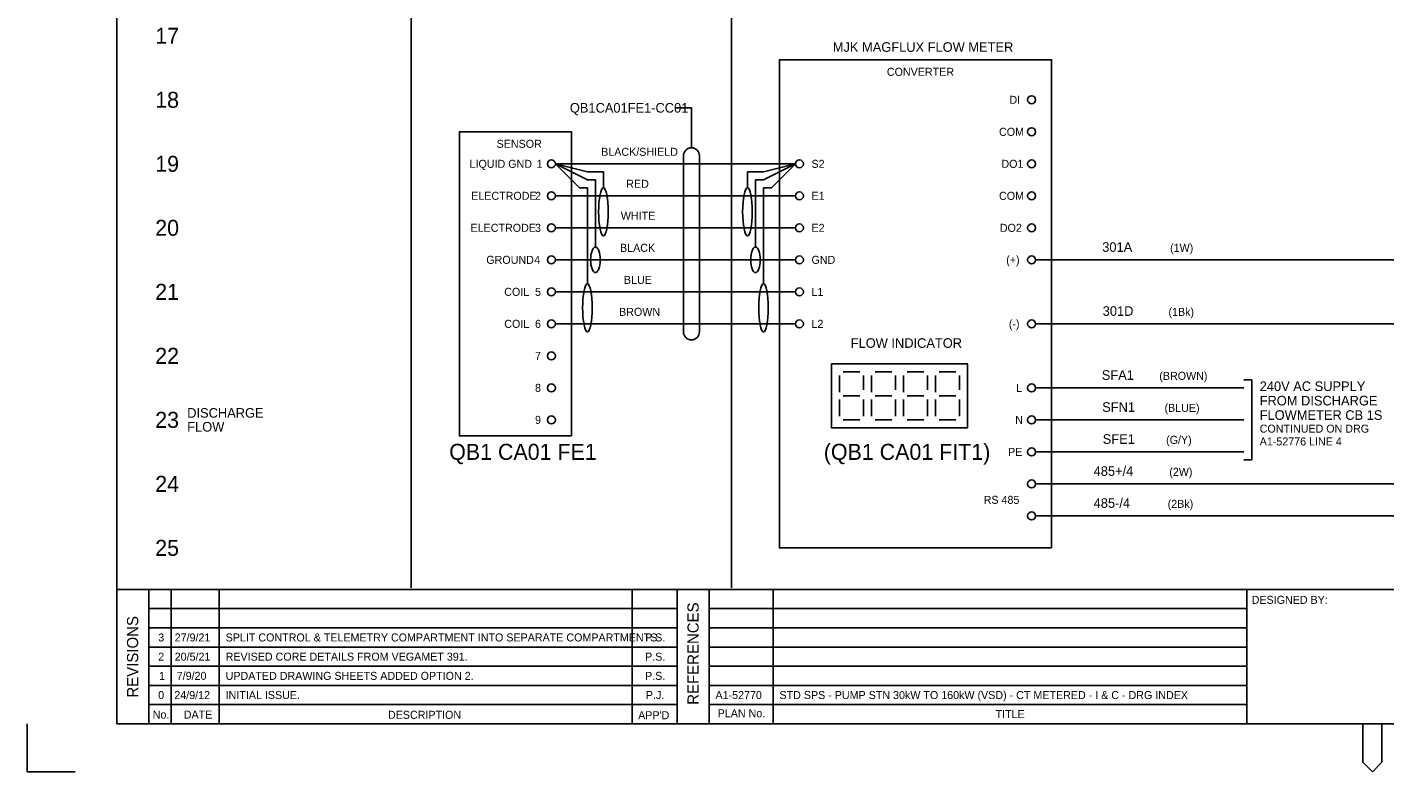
# Model space of a CAD drawing. Extents: x 0 to 841, y 0 to 594.
# Drawn here: x 0 to 424.1, y 0 to 232.7 of the extents above; entities that cross this region are included whole.
import ezdxf

# ---------------------------------------------------------------- set-up
doc = ezdxf.new("R2010")
doc.units = 0
for name, color, linetype in [('A1BORDER', 7, 'Continuous'), ('Level 1', 7, 'Continuous'), ('Level 10', 7, 'Continuous'), ('Level 2', 7, 'Continuous')]:
    doc.layers.add(name, color=color, linetype=linetype)

msp = doc.modelspace()

# ---------------------------------------------------------------- linework, layer by layer
at = {"layer": 'A1BORDER'}
for p, q in [((28, 581), (28, 15)), ((28, 57), (829, 57)), ((38, 15), (38, 57)), ((45, 15), (45, 57)), ((60, 15), (60, 57)), ((189, 15), (189, 57)), ((203, 15), (203, 57)), ((213, 15), (213, 57)), ((233, 15), (233, 57)), ((381, 15), (381, 57)), ((203, 51), (38, 51)), ((213, 51), (381, 51)), ((203, 45), (38, 45)), ((213, 45), (381, 45)), ((203, 39), (38, 39)), ((213, 39), (381, 39)), ((203, 33), (38, 33)), ((213, 33), (381, 33)), ((38, 27), (203, 27)), ((213, 27), (381, 27)), ((203, 21), (38, 21)), ((213, 21), (381, 21)), ((0, 0), (0, 15)), ((829, 15), (28, 15)), ((417.19, 15), (417.19, 3)), ((423.19, 15), (423.19, 3)), ((0, 0), (15, 0)), ((417.19, 3), (420.19, 0)), ((423.19, 3), (420.19, 0))]:
    msp.add_line(p, q, dxfattribs=at)
at = {"layer": 'Level 1'}
for p, q in [((120, 57.5), (120, 581)), ((220, 57.5), (220, 581)), ((312.5, 210), (312.5, 210)), ((315, 210), (315, 210)), ((207.5, 207.5), (202.5, 207.5)), ((207.5, 207.5), (207.5, 195)), ((312.5, 200), (312.5, 200)), ((315, 200), (315, 200)), ((205, 192.5), (205, 137.5)), ((210, 192.5), (210, 137.5)), ((162.5, 190), (162.5, 190)), ((240, 190), (165, 190)), ((165, 190), (165, 190)), ((175, 187.5), (165, 190)), ((175, 185), (165, 190)), ((172.5, 182.5), (165, 190)), ((180, 187.5), (175, 187.5)), ((180, 182.5), (180, 187.5)), ((225, 182.5), (225, 187.5)), ((225, 187.5), (230, 187.5)), ((230, 187.5), (240, 190)), ((230, 185), (240, 190)), ((232.5, 182.5), (240, 190)), ((240, 190), (240, 190)), ((242.5, 190), (242.5, 190)), ((312.5, 190), (312.5, 190)), ((315, 190), (315, 190)), ((175, 182.5), (172.5, 182.5)), ((175, 185), (177.5, 185)), ((175, 152.5), (175, 182.5)), ((177.5, 164), (177.5, 185)), ((227.5, 164), (227.5, 185)), ((230, 185), (227.5, 185)), ((230, 152.5), (230, 182.5)), ((230, 182.5), (232.5, 182.5)), ((162.5, 180), (162.5, 180)), ((240, 180), (165, 180)), ((165, 180), (165, 180)), ((240, 180), (240, 180)), ((242.5, 180), (242.5, 180)), ((312.5, 180), (312.5, 180)), ((315, 180), (315, 180)), ((162.5, 170), (162.5, 170)), ((240, 170), (165, 170)), ((165, 170), (165, 170)), ((240, 170), (240, 170)), ((242.5, 170), (242.5, 170)), ((312.5, 170), (312.5, 170)), ((315, 170), (315, 170)), ((162.5, 160), (162.5, 160)), ((165, 160), (165, 160)), ((177.5, 160), (165, 160)), ((240, 160), (165, 160)), ((240, 160), (240, 160)), ((242.5, 160), (242.5, 160)), ((312.5, 160), (312.5, 160)), ((315, 160), (315, 160)), ((602.5, 160), (315, 160)), ((162.5, 150), (162.5, 150)), ((240, 150), (165, 150)), ((165, 150), (165, 150)), ((240, 150), (240, 150)), ((242.5, 150), (242.5, 150)), ((162.5, 140), (162.5, 140)), ((240, 140), (165, 140)), ((165, 140), (165, 140)), ((240, 140), (240, 140)), ((242.5, 140), (242.5, 140)), ((312.5, 140), (312.5, 140)), ((315, 140), (315, 140)), ((602.5, 140), (315, 140)), ((162.5, 130), (162.5, 130)), ((165, 130), (165, 130)), ((162.5, 120), (162.5, 120)), ((165, 120), (165, 120)), ((312.5, 120), (312.5, 120)), ((315, 120), (315, 120)), ((315, 120), (380, 120)), ((162.5, 110), (162.5, 110)), ((165, 110), (165, 110)), ((312.5, 110), (312.5, 110)), ((315, 110), (315, 110)), ((315, 110), (380, 110)), ((312.5, 100), (312.5, 100)), ((315, 100), (315, 100)), ((315, 100), (380, 100)), ((315, 90), (602.5, 90)), ((315, 80), (602.5, 80))]:
    msp.add_line(p, q, dxfattribs=at)
for points in [[(320, 70), (235, 70), (235, 222.5), (320, 222.5)], [(170, 105), (135, 105), (135, 200), (170, 200)], [(251.25, 127.5), (293.75, 127.5), (293.75, 107.5), (251.25, 107.5)]]:
    msp.add_lwpolyline(points, close=True, dxfattribs=at)
msp.add_lwpolyline([(380, 122.5), (382.5, 122.5), (382.5, 97.5), (380, 97.5)], dxfattribs=at)
for centre, start, end in [((207.5, 192.5), 0, 180), ((207.5, 137.5), 180, 0)]:
    msp.add_arc(centre, 2.5, start, end, dxfattribs=at)
for centre, major_axis, ratio in [((180, 175), (0, -7.5), 0.2), ((225, 175), (0, 7.5), 0.2), ((177.5, 160), (0, -4), 0.375), ((227.5, 160), (0, 4), 0.375), ((175, 145), (0, -7.5), 0.2), ((230, 145), (0, 7.5), 0.2)]:
    msp.add_ellipse(centre, major_axis=major_axis, ratio=ratio, dxfattribs=at)
at = {"layer": 'Level 10'}
for centre in [(313.75, 210), (313.75, 200), (163.75, 190), (241.25, 190), (313.75, 190), (163.75, 180), (241.25, 180), (313.75, 180), (163.75, 170), (241.25, 170), (313.75, 170), (163.75, 160), (241.25, 160), (313.75, 160), (163.75, 150), (241.25, 150), (163.75, 140), (241.25, 140), (313.75, 140), (163.75, 130), (163.75, 120), (313.75, 120), (163.75, 110), (313.75, 110), (313.75, 100), (313.75, 90), (313.75, 80)]:
    msp.add_circle(centre, 1.25, dxfattribs=at)
at = {"layer": 'Level 2'}
for p, q in [((253.75, 123.88), (253.75, 118.63)), ((254.88, 125), (260.12, 125)), ((261.25, 123.88), (261.25, 119.38)), ((263.75, 123.88), (263.75, 118.63)), ((264.88, 125), (270.12, 125)), ((271.25, 123.88), (271.25, 119.38)), ((273.75, 123.88), (273.75, 118.63)), ((274.88, 125), (280.12, 125)), ((281.25, 123.88), (281.25, 119.38)), ((283.75, 123.88), (283.75, 118.63)), ((284.88, 125), (290.12, 125)), ((291.25, 123.88), (291.25, 119.38)), ((253.75, 116.38), (253.75, 111.13)), ((254.88, 117.5), (260.12, 117.5)), ((261.25, 116.38), (261.25, 111.13)), ((263.75, 116.38), (263.75, 111.13)), ((264.88, 117.5), (270.12, 117.5)), ((271.25, 116.38), (271.25, 111.13)), ((273.75, 116.38), (273.75, 111.13)), ((274.88, 117.5), (280.12, 117.5)), ((281.25, 116.38), (281.25, 111.13)), ((283.75, 116.38), (283.75, 111.13)), ((284.88, 117.5), (290.12, 117.5)), ((291.25, 116.38), (291.25, 111.13)), ((254.88, 110), (260.12, 110)), ((264.88, 110), (270.12, 110)), ((274.88, 110), (280.12, 110)), ((284.88, 110), (290.12, 110))]:
    msp.add_line(p, q, dxfattribs=at)

# ---------------------------------------------------------------- texts
at = {"layer": 'A1BORDER'}
for s, p in [('REFERENCES', (209.76, 20.96)), ('REVISIONS', (34.68, 23.2))]:
    msp.add_text(s, height=3.5, rotation=90, dxfattribs=at).set_placement(p)
for s, p in [('DESIGNED BY:', (382.5, 52.5)), ('No.', (39.21, 16.65)), ('DATE', (48.92, 16.65)), ('DESCRIPTION', (112.71, 16.57)), ("APP'D", (190.85, 16.44)), ('PLAN No.', (215.69, 17.06)), ('TITLE', (302.5, 16.81))]:
    msp.add_text(s, height=2.5, dxfattribs=at).set_placement(p)
at = {"layer": 'Level 1'}
for s, height, p in [('17', 5, (40, 227.5)), ('MJK MAGFLUX FLOW METER', 3, (251.65, 225)), ('MJK MAGFLUX FLOW METER', 3, (251.65, 225)), ('CONVERTER', 2.5, (268.55, 217.5)), ('18', 5, (40, 207.5)), ('QB1CA01FE1-CC01', 3, (169.52, 206)), ('DI', 2.5, (306.81, 208.75)), ('COM', 2.5, (303.58, 198.75)), ('SENSOR', 2.5, (146.64, 195)), ('BLACK/SHIELD', 2.5, (179.3, 192.5)), ('19', 5, (40, 187.5)), ('LIQUID GND', 2.5, (138.2, 188.75)), ('1', 2.5, (159.13, 188.75)), ('S2', 2.5, (245, 188.75)), ('DO1', 2.5, (304.32, 188.75)), ('RED', 2.5, (187.14, 182.5)), ('ELECTRODE', 2.5, (138.69, 178.75)), ('2', 2.5, (158.64, 178.75)), ('E1', 2.5, (245, 178.75)), ('COM', 2.5, (303.58, 178.75)), ('WHITE', 2.5, (185.44, 172.5)), ('20', 5, (40, 167.5)), ('ELECTRODE', 2.5, (138.49, 168.75)), ('3', 2.5, (158.64, 168.75)), ('E2', 2.5, (245, 168.75)), ('DO2', 2.5, (303.83, 168.75)), ('301A', 3, (335.82, 162.5)), ('GROUND', 2.5, (143.42, 158.75)), ('4', 2.5, (158.39, 158.75)), ('BLACK', 2.5, (185.19, 162.5)), ('GND', 2.5, (245, 158.75)), ('(+)', 2.5, (305.82, 158.75)), ('(1W)', 2.5, (357.01, 162.5)), ('BLUE', 2.5, (186.41, 152.5)), ('21', 5, (40, 147.5)), ('COIL', 2.5, (149.02, 148.75)), ('5', 2.5, (158.64, 148.75)), ('L1', 2.5, (245, 148.75)), ('BROWN', 2.5, (184.9, 142.5)), ('301D', 3, (335.96, 142.5)), ('(1Bk)', 2.5, (356.51, 142.5)), ('COIL', 2.5, (149.03, 138.75)), ('6', 2.5, (158.64, 138.75)), ('L2', 2.5, (245, 138.75)), ('(-)', 2.5, (306.64, 138.75)), ('22', 5, (40, 127.5)), ('7', 2.5, (158.64, 128.75)), ('SFA1', 3, (335.67, 122.5)), ('(BROWN)', 2.5, (353.65, 122.5)), ('8', 2.5, (158.64, 118.75)), ('L', 2.5, (308.88, 118.75)), ('240V AC SUPPLY', 3, (385, 119)), ('SFN1', 3, (335.81, 112.5)), ('(BLUE)', 2.5, (355.27, 112.5)), ('FROM DISCHARGE', 3, (385, 114.5)), ('23', 5, (40, 107.5)), ('DISCHARGE', 3, (50, 110.67)), ('9', 2.5, (158.64, 108.75)), ('N', 2.5, (308.62, 108.75)), ('FLOWMETER CB 1S', 3, (385, 110)), ('FLOW', 3, (50, 106.33)), ('CONTINUED ON DRG', 2.5, (385, 106)), ('QB1 CA01 FE1', 5, (131.83, 97.5)), ('(QB1 CA01 FIT1)', 5, (248.84, 97.5)), ('SFE1', 3, (335.97, 102.5)), ('(G/Y)', 2.5, (355.77, 102.5)), ('A1-52776 LINE 4', 2.5, (385, 102)), ('PE', 2.5, (306.41, 98.75)), ('485+/4', 3, (333.13, 92.5)), ('(2W)', 2.5, (356.76, 92.5)), ('24', 5, (40, 87.5)), ('RS 485', 2.5, (298.79, 83.75)), ('485-/4', 3, (333.13, 82.5)), ('(2Bk)', 2.5, (356.26, 82.5)), ('25', 5, (40, 67.5)), ('3', 2.5, (40.94, 40.75)), ('27/9/21', 2.5, (46.09, 40.75)), ('SPLIT CONTROL & TELEMETRY COMPARTMENT INTO SEPARATE COMPARTMENTS.', 2.5, (62, 40.75)), ('P.S.', 2.5, (193.02, 40.75)), ('2', 2.5, (40.94, 34.75)), ('20/5/21', 2.5, (46.09, 34.75)), ('REVISED CORE DETAILS FROM VEGAMET 391.', 2.5, (62, 34.75)), ('P.S.', 2.5, (193.02, 34.75)), ('1', 2.5, (41.19, 28.75)), ('7/9/20', 2.5, (46.72, 28.75)), ('UPDATED DRAWING SHEETS ADDED OPTION 2.', 2.5, (62, 28.75)), ('P.S.', 2.5, (193.02, 28.75)), ('0', 2.5, (40.94, 22.75)), ('24/9/12', 2.5, (45.97, 22.75)), ('INITIAL ISSUE.', 2.5, (62, 22.75)), ('P.J.', 2.5, (193.26, 22.75)), ('A1-52770', 2.5, (215, 22.75)), ('STD SPS - PUMP STN 30kW TO 160kW (VSD) - CT METERED - I & C - DRG INDEX', 2.5, (235, 22.75))]:
    msp.add_text(s, height=height, dxfattribs=at).set_placement(p)
at = {"layer": 'Level 2'}
msp.add_text('FLOW INDICATOR', height=3, dxfattribs=at).set_placement((257.26, 132.5))

doc.saveas('drawing.dxf')
